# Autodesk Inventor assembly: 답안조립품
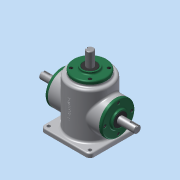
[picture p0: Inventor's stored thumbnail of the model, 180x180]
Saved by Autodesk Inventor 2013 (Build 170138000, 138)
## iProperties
Created: 2015-10
Part Number: 답안조립품
Document SubType Name: Assembly
Designer: dgall
Author: dgall
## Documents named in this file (14)
- C:\Users\dgall\Desktop\451007V1029\답안조립품.iam
- C:\Users\dgall\Desktop\451007V1029\본체.ipt
- C:\Users\dgall\Desktop\451007V1029\메인 축.ipt
- 메인 축.ipt
- C:\Users\dgall\Desktop\451007V1029\키 5x5.ipt
- C:\Users\dgall\Desktop\451007V1029\메인 베벨기어.ipt
- C:\Users\dgall\Desktop\451007V1029\베어링 6203.ipt
- C:\Users\dgall\Desktop\451007V1029\커버.ipt
- C:\Users\dgall\Desktop\451007V1029\오일실.ipt
- C:\Users\dgall\Desktop\451007V1029\서브 축.ipt
- 서브 축.ipt
- C:\Users\dgall\Desktop\451007V1029\서브 베벨기어.ipt
- C:\Users\dgall\Desktop\451007V1029\키 4x4.ipt
- C:\Users\dgall\Desktop\451007V1029\M4.ipt
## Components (12 placed, 1 different names)
1. M4:1
2. M4:2
3. M4:3
4. M4:4
5. M4:5
6. M4:6
7. M4:7
8. M4:8
9. M4:9
10. M4:10
11. M4:11
12. M4:12
